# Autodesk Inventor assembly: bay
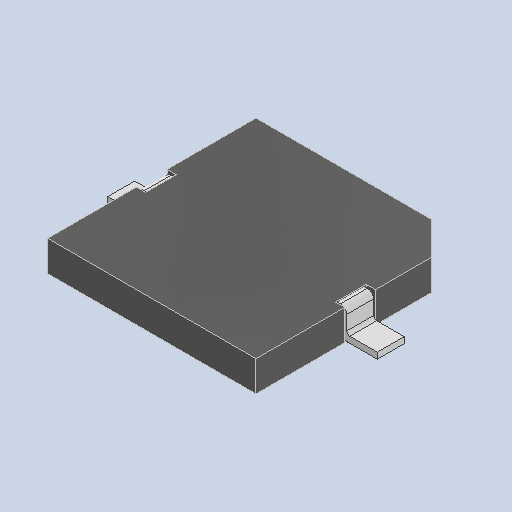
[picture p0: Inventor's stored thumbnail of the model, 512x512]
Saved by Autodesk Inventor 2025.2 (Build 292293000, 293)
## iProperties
Created: 2025-04
Part Number: bay
Description: PART--DESC
Document SubType Name: Assembly
Designer: BennF
Author: BennF
Revision Number: NONE
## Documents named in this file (3)
- C:\Users\BennF\Nextcloud\Benutzer\CNC JarBeRi\existing parts\Electronics\RepRap A4988 Shied (USE WITHOUT ARDUINO)\reprap-a4988-1.snapshot.1\RepRap\RepRap\bay.iam
- C:\Users\BennF\Nextcloud\Benutzer\CNC JarBeRi\existing parts\Electronics\RepRap A4988 Shied (USE WITHOUT ARDUINO)\reprap-a4988-1.snapshot.1\RepRap\RepRap\bay Geometry.ipt
- C:\Users\BennF\Nextcloud\Benutzer\CNC JarBeRi\existing parts\Electronics\RepRap A4988 Shied (USE WITHOUT ARDUINO)\reprap-a4988-1.snapshot.1\RepRap\RepRap\pin14.ipt
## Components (2 placed, 2 different names)
1. bay Geometry
2. pin14
